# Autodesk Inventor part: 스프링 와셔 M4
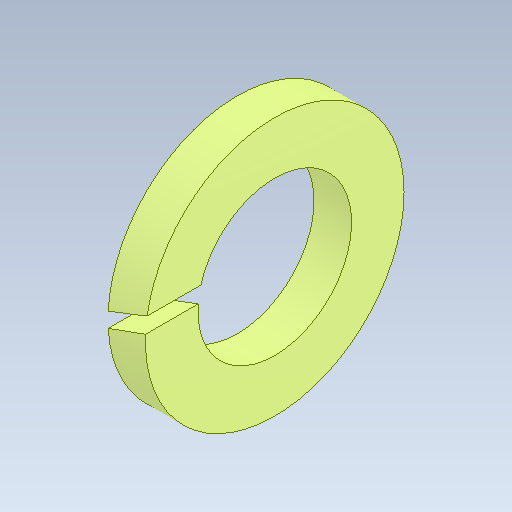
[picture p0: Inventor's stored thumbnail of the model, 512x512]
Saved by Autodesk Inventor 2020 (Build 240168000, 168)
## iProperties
Created: 2024-07
Part Number: 스프링 와셔 M4
Material: 강철, 연강
Description: 스프링 잠금 와셔
Document SubType Name: Modeling
Designer: oem
Density: 7.85 g/cm^3
Appearance: 기본값
Author: jhkim
Sending System: Autodesk Inventor 2025
Preprocessor: ST-DEVELOPER v20
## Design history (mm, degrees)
feature "Solid1"
node "솔리드1"
